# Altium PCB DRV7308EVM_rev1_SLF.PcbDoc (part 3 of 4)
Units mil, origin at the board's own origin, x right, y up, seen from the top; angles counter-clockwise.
Board outline 6187 x 6000 mil, 4 copper layers (Top Layer, Ground, Power, Bottom Layer), stack 61.2 mil thick; 306 components, 128 nets, 676 pads, 1026 vias.
Unrouted connection lines stored in the file: 208.
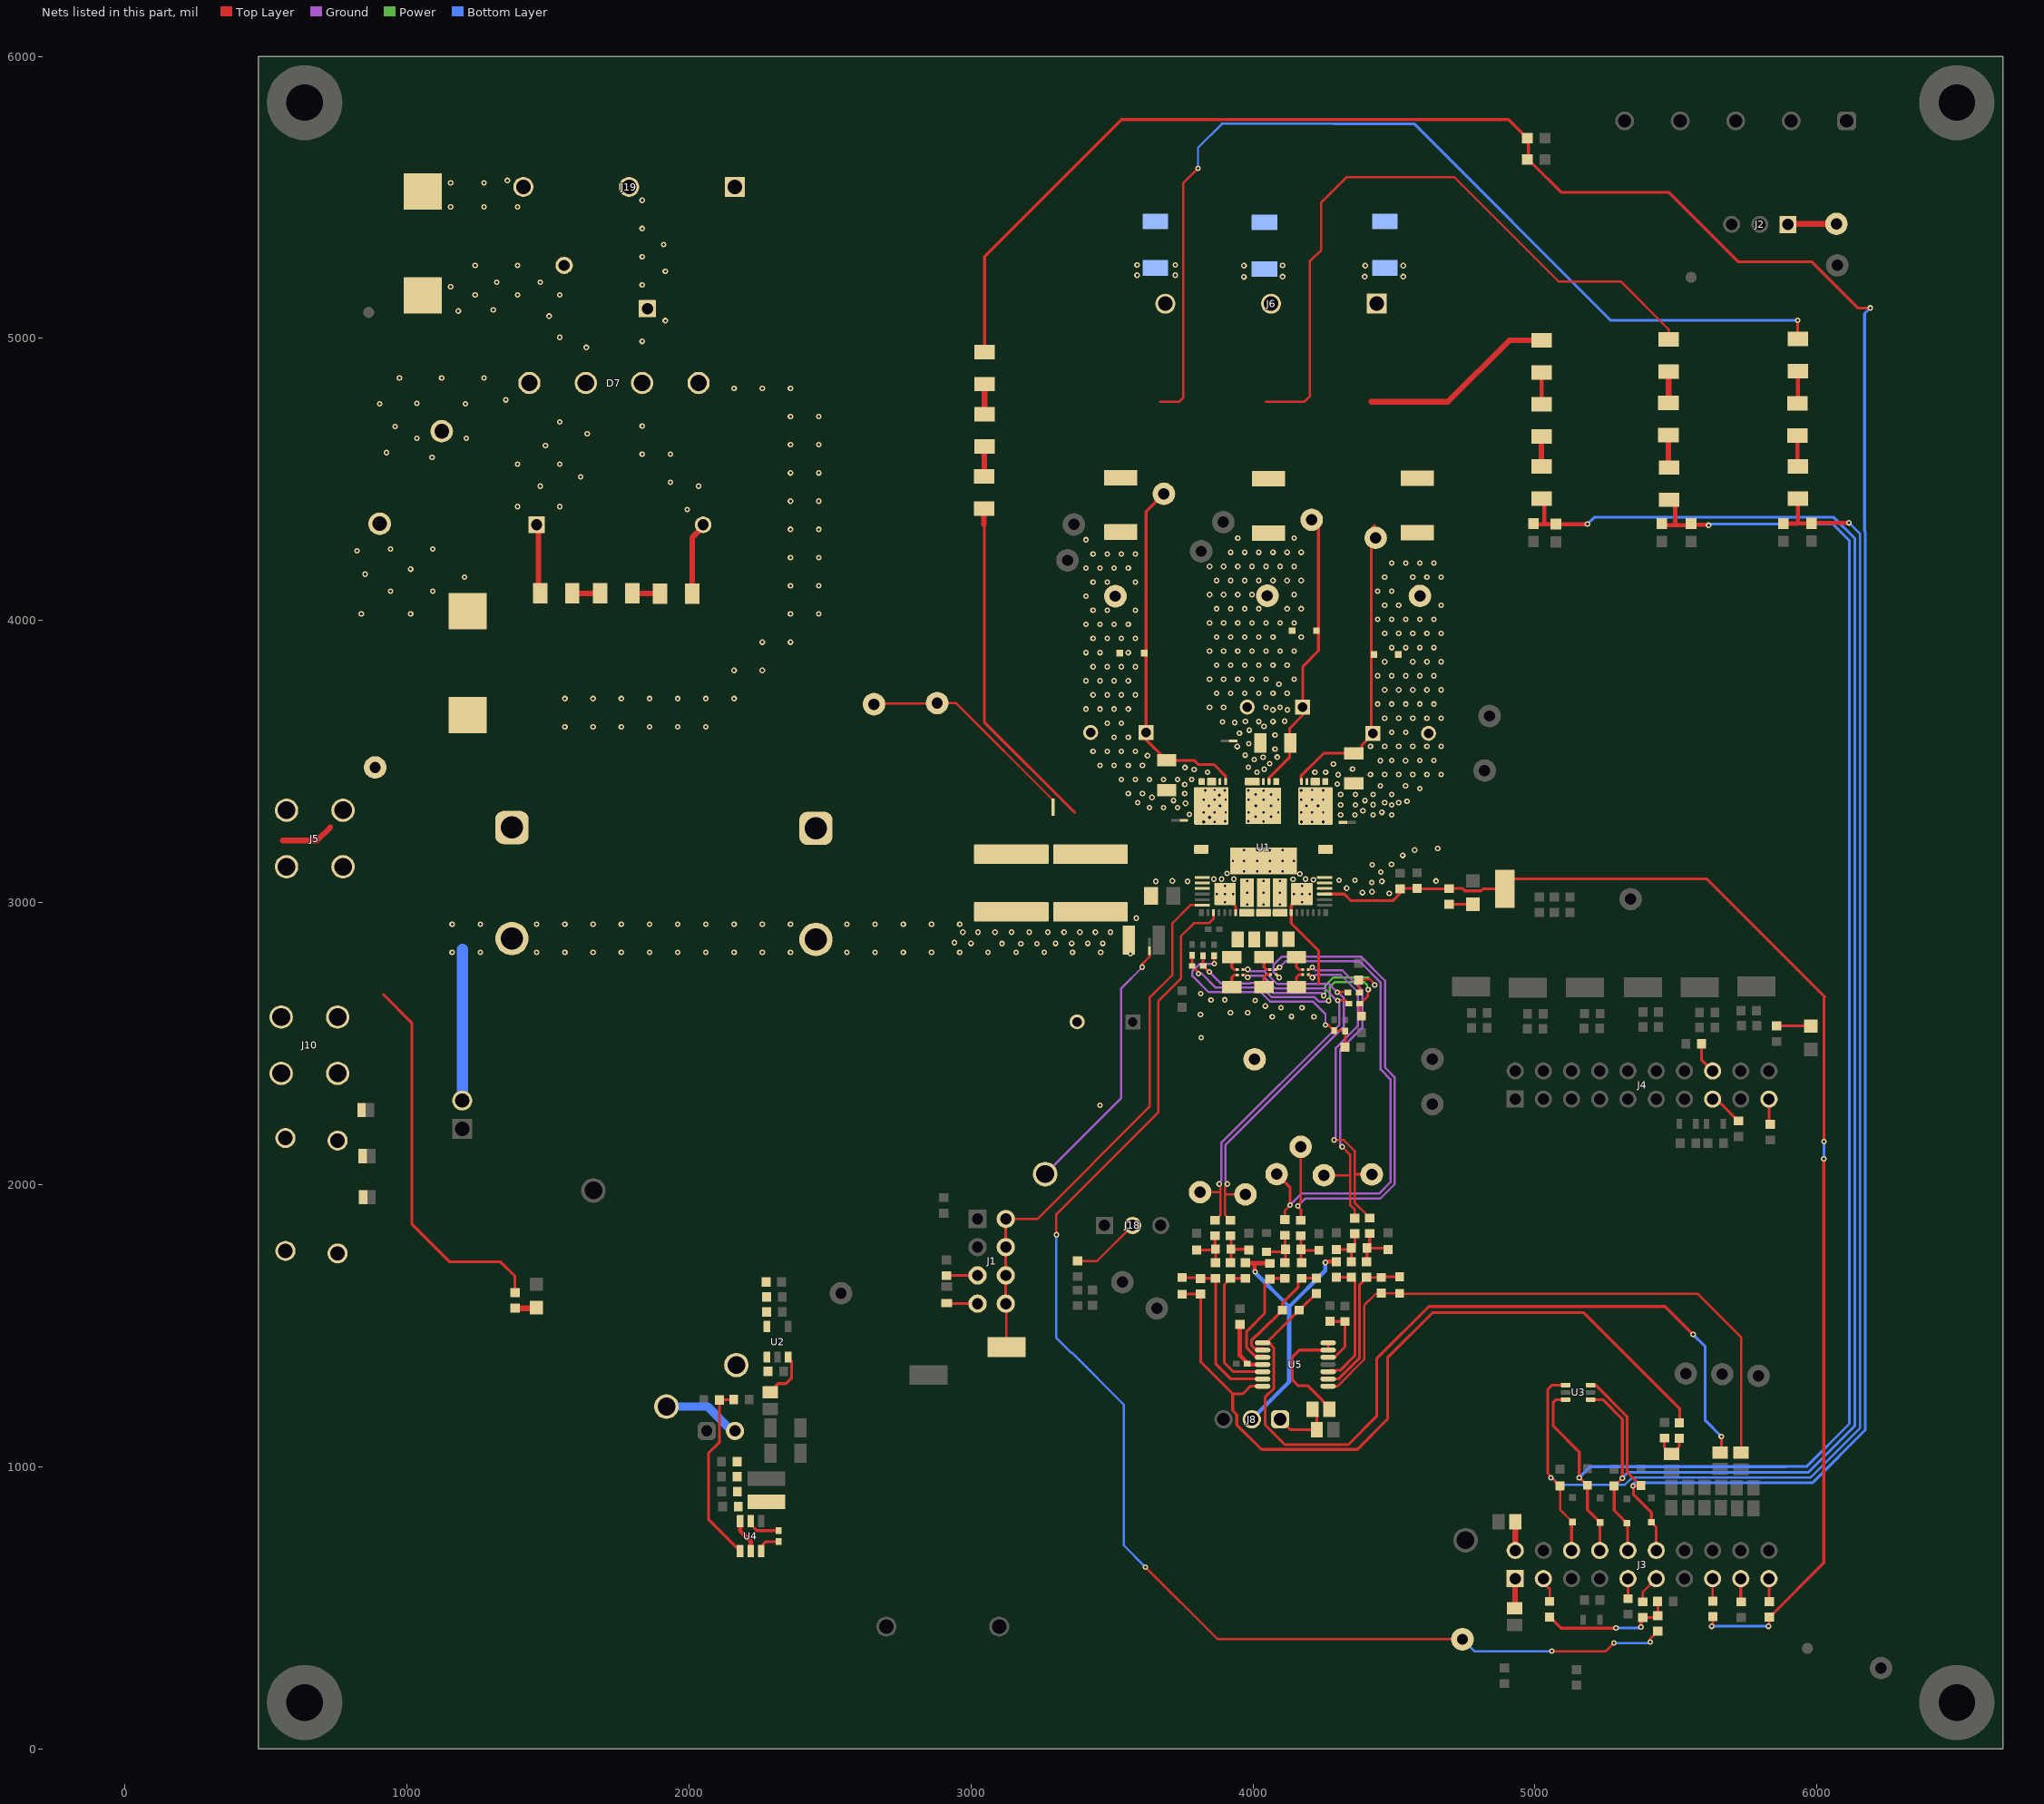
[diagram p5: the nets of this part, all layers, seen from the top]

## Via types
v1: diameter 20, hole 10, Top Layer to Bottom Layer, tented both sides, 563 vias
v2: diameter 20/20/20/20 (per signal layer), hole 10, Top Layer to Bottom Layer, tented both sides, 370 vias
v3: diameter 19.68, hole 7.87, Top Layer to Bottom Layer, tented both sides, 57 vias
v4: diameter 39.37, hole 19.68, Top Layer to Bottom Layer, tented both sides, 24 vias
v5: diameter 20/20/20/20 (per signal layer), hole 10, Top Layer to Bottom Layer, tented bottom, 12 vias

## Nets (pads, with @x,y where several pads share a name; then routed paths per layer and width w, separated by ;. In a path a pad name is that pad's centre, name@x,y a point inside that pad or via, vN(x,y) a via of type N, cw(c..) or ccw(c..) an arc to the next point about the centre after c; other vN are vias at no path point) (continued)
NetC1_2: C1.2 C59.1 D14.1 TP29.1 U1.48 | length 1252.7
  Top Layer w10: TP29.1@3684,4449 3621,4386 3621,3881 3621,3869.06 C59.1@3621,3603 3621,3577.15 C1.2@3694,3504.15 3790.85,3504.15 3805.61,3489.39 3861.82,3489.39 3902.58,3448.63 U1.48@3902.58,3428.66
NetC2_1: C2.1 L1.1 U4.2 | length 120.4
  Top Layer w10: U4.2@2218.7,806.82 2218.7,794.74 2240.27,773.17 2317.73,773.17 C2.1@2318,773.44
NetC2_2: C2.2 U4.6 | length 85.8
  Top Layer w10: U4.6@2256.11,700.52 2256.11,717.55 2272.63,734.07 C2.2@2318,734.07
NetC3_2: C3.2 C60.1 D16.1 TP32.1 U1.43 | length 984.9
  Top Layer w10: U1.43@4056.76,3428.66 4056.76,3441.76 4130.5,3515.5 4130.5,3566 4130.5,3618.15 4176.76,3664.41 4176.76,3693 4176.76,3837.76 4177,3838 4232,3893 4232,3964 TP32.1@4232,4341
NetC4_1: C4.1 J8.1 R14.2 | length 225.3
  Top Layer w10: J8.1@4095.7,1168 4132.7,1131 C4.1@4226.47,1131 4226.47,1189 R14.2@4211.47,1204
NetC5_2: C5.2 C61.1 D15.1 TP34.1 U1.41 | length 1089.8
  Top Layer w10: U1.41@4170.93,3428.66 4170.93,3449.52 4250.56,3529.15 4369,3529.15 4385.66,3545.8 4385.66,3557.81 4404,3576.15 4404,3578.43 C61.1@4425.57,3600 4419.15,3606.43 4419.15,3867 4419.15,4177 4419.15,4324.15 4431,4336
NetC7_1: C7.1 C29.1 C30.1 C31.1 J17.2 TP33.1 U4.3 U4.5 | length 400.6
  Top Layer w15: U4.3@2181.3,806.82 2181.3,773.86 2218.7,736.46 U4.5@2218.7,700.52
  Bottom Layer w30: TP33.1@1920,1213 2065.83,1213 2152.39,1126.44 J17.2@2163,1126.44
NetC11_1: C11.1 C12.2 R9.2 R10.1 | length 864.4
  Top Layer w8: C12.2@4374,2724.44 4376.37,2722.07 R9.2@4376.37,2681 ; C12.2@4374,2727.44 4415.24,2727.44 4420.9,2721.78 4420.9,2721 4431.61,2710.29 v1(4431.61,2707.04)
  Top Layer w10: R10.1@3823,2811.32 3823,2775.69 C11.1@3823.68,2775 3844.82,2753.87 v1(3845,2753.87)
  Ground w8: v1@3847.13,2753.87 v1(3845,2753.87) 3885.33,2713.54 3989.89,2713.54 3991.35,2715 4037.92,2715 4072.84,2680.08 4242.77,2680.08 4251.77,2671.08 v1(4250.5,2669.81)
  Power w8: v1(4250.5,2669.81) 4250.5,2673.05 4256.5,2679.05 4256.5,2705.89 4284.61,2734 4408.48,2734 4429.31,2713.17 4429.31,2712.59 4431.61,2710.29 v1(4431.61,2707.04)
NetC11_2: C11.2 C36.1 R11.2 R12.1 | length 888.5
  Top Layer w8: R11.2@4378.69,2642 4378.69,2603.84 C36.1@4385,2597.53 ; R11.2@4380.65,2642 4408.07,2669.42 4408.07,2690.72 v1(4408.78,2691.42)
  Top Layer w10: R12.1@3784,2812.32 3784.31,2812 C11.2@3784.31,2775 3807,2752.31 v1(3807,2748)
  Ground w8: v1(3807,2748) 3816,2748 3817,2749 3867.92,2698.08 4032.98,2698.08 4066.44,2664.62 4218.24,2664.62 4234.52,2648.35 v1@4259.39,2648.35
  Power w8: v1(4268,2652) 4268,2655.25 4271.96,2659.2 4271.96,2699.48 4291.01,2718.54 4393.59,2718.54 4404.99,2707.14 4404.99,2698.45 4408.78,2694.67 v1(4408.78,2691.42)
NetC17_1: C17.1 R46.1 R53.2 U5.2 | length 423.4
  Top Layer w10: U5.2@4034.12,1413.33 4038.85,1418.06 4006.77,1418.06 3994.56,1430.28 3994.56,1447.56 4013,1466 4015.47,1466 C17.1@4104.47,1555 4104.47,1580.36 4160.83,1636.71 4160.83,1656.69 4171.57,1667.44 R53.2@4172.56,1667.44 4173.68,1668.56 R46.1@4226.56,1668.56
NetC24_1: C24.1 R58.1 R60.2 U5.6 | length 612
  Top Layer w10: C24.1@3749,1670.53 3810.43,1670.53 R58.1@3814.26,1666.7 3815.14,1667.59 R60.2@3867.26,1667.59 3867.26,1364.99 3921.29,1310.96 U5.6@4034.12,1310.96
NetC28_1: C28.1 C33.1 R54.1 U2.5
NetC37_2: C37.2 C39.1 R52.2 R53.1 | length 162.2
  Top Layer w10: R52.2@4169.56,1818.44 4169.56,1770.56 C39.1@4170.12,1770 ; R53.1@4172.56,1722.56 4170.12,1725 C39.1@4170.12,1770 ; C37.2@4234,1767 4173.12,1767 C39.1@4170.12,1770
NetC38_2: C38.2 R47.1 U5.4 | length 205.9
  Top Layer w15: R47.1@3953.26,1504.59 3953.26,1394.62 3979.94,1367.93 C38.2@3979.94,1365.14 3982.94,1362.14 U5.4@4034.12,1362.14
NetC39_2: C39.2 C40.1 R55.2 R56.1 | length 169.3
  Top Layer w10: C40.1@4048.26,1761.68 4106.68,1761.68 C39.2@4115,1770 ; R56.1@4113.56,1722.56 4115,1724 C39.2@4115,1770 ; R55.2@4113.56,1820.44 4113.56,1771.44 C39.2@4115,1770
NetC41_2: C41.2 C42.1 R59.2 R60.1 | length 164.5
  Top Layer w10: C41.2@3800,1768.47 3864.03,1768.47 C42.1@3866.7,1771.14 ; R59.2@3865.26,1818.59 3865.26,1772.59 C42.1@3866.7,1771.14 ; R60.1@3867.26,1722.7 3867.26,1770.59 C42.1@3866.7,1771.14
NetC42_2: C42.2 C43.1 R61.2 R62.1 | length 162.7
  Top Layer w10: R62.1@3920.26,1722.7 3921.82,1724.26 C42.2@3921.82,1771.14 ; R61.2@3920.26,1818.59 3921.82,1817.03 C42.2@3921.82,1771.14 ; C43.1@3985,1768.47 3985,1770.59 3922.37,1770.59 C42.2@3921.82,1771.14
NetC44_2: C44.2 C45.1 R65.2 R66.1 | length 181.6
  Top Layer w10: R66.1@4402.56,1726.56 4404.12,1728.12 C45.1@4404.12,1775 ; R65.2@4414,1826.44 4414,1784.88 C45.1@4404.12,1775 ; C44.2@4479,1770 4474,1775 C45.1@4404.12,1775
NetC45_2: C45.2 C46.1 R67.2 R68.1 | length 159.7
  Top Layer w10: C46.1@4296,1770 4344,1770 C45.2@4349,1775 ; R68.1@4348.56,1726.56 4349,1727 C45.2@4349,1775 ; R67.2@4361,1826 4361,1787.98 4349,1775.98 C45.2@4349,1775
NetC50_1: C50.1 R64.1 R66.2 U5.9 | length 557.3
  Top Layer w8: R66.2@4403.44,1670.56 R64.1@4455.56,1670.56
  Top Layer w10: U5.9@4266.4,1310.96 4303.15,1310.96 4378.26,1386.07 4378.26,1645.37 4390.83,1657.94 4390.83,1660.69 4400.69,1670.56 R66.2@4403.44,1670.56 ; R64.1@4455.56,1670.56 4457.91,1672.91 C50.1@4520.3,1672.91
NetC52_2: C52.2 R8.1 R45.2 R129.2 | length 836.7
  Top Layer w8: R45.2@3862,2811.31 3862,2784 v1(3863,2783) ; v1(4257,2566) 4267.32,2566 R8.1@4288,2545.32 4326,2545.32 R129.2@4327,2544.31 4327,2487.56 C52.2@4326.44,2487
  Ground w8: v1(3863,2783) 3811.65,2783 3785.54,2756.89 3785.54,2739.11 3842.03,2682.62 4026.58,2682.62 4060.04,2649.16 4211.84,2649.16 4257,2604 v1(4257,2566)
NetC56_1: C56.1 D7.2 F1.1 R121.2 RV1.2 | length 248.4
  Top Layer w20: C56.1@1459.72,4339.36 1465.82,4333.26 1465.82,4102.09 R121.2@1471.91,4096
  other v1: 1473,4476 1616,4509 1491,4620 1639,4662 1636,4968 1504,5079 1182,5097 1306,5101 1155,5183 1318,5199 1473,5199 1241.77,5258.77 1391.77,5258.77
  other v2: 1391.77,4403.7 1541.77,4403.7 1391.77,4553.7 1541.77,4553.7 1541.77,4703.7 1541.77,5003.7 1241.77,5153.7 1391.77,5153.7 1541.77,5153.7
NetC56_2: C56.2 D7.3 J19.2 R122.1 RV1.1 | length 260.4
  Top Layer w20: R122.1@2011.5,4095 2011.5,4293.95 2050.28,4332.72 C56.2@2050.28,4339.36
  other v1: 1994,4393 2034,4476 1916,5063 1916,5238 1910,5333
  other v2: 1934,4489.55 1834,4589.55 1934,4589.55 1834,4689.55 1834,4989.55 1834,5189.55 1834,5289.55 1834,5389.55 1834,5489.55
NetD2_2: D2.2 R15.2 | length 85.1
  Top Layer w10: R15.2@4695,2993.86 4779.78,2993.86 D2.2@4780,2994.08
NetD3_2: D3.2 R16.2 | length 65.5
  Top Layer w20: R16.2@1394.56,1561.34 1456.34,1561.34 D3.2@1459,1564
NetD4_2: D4.2 R17.2 | length 132.1
  Top Layer w10: R17.2@5848.99,2555.69 R17.2@5856.54,2563.24 ; R17.2@5857.19,2562.59 5977.45,2562.59 D4.2@5978.28,2561.76
NetD7_1: D7.1 RT1.1
  other v1: 1089,4578 927,4595 1035,4646 1210,4646 958,4688 903,4768 1207,4768 1035,4770 1350,4782
  other v2: 973,4859.82 1123,4859.82 1273,4859.82
NetF1_2: F1.2 J19.3
  other v1: 1155,5466 1273,5466 1391.77,5466 1155,5551 1273,5551 1356,5560
NetF2_1: F2.1 RT1.2
  other v1: 838,4023 1013,4023 1204,4154 852,4164 1013,4182 823,4247
  other v2: 941.77,4103.7 1091.77,4103.7 941.77,4253.7 1091.77,4253.7
NetJ1_5: J1.5 R43.2 | length 110.2
  Top Layer w10: R43.2@2913.23,1677.44 2913.79,1678 J1.5@3023.23,1678
NetJ1_7: J1.7 R44.2 | length 109.6
  Top Layer w10: R44.2@2914.23,1579.47 2915.7,1578 J1.7@3023.23,1578
NetJ2_1: J2.1 TP52.1 | length 181.1
  Top Layer w20: J2.1@5897,5404 5899,5406 TP52.1@6069,5406 TP52.1@6074.87,5411.87
NetJ3_1: J3.1 R13.2 | length 105.7
  Top Layer w20: R13.2@4927.82,498.13 4929.82,500.13 J3.1@4929.82,603
NetJ3_2: J3.2 R36.1 | length 102.2
  Top Layer w20: J3.2@4929.82,703 4929.93,703.11 4929.93,804.59 R36.1@4930.35,805
NetJ3_3: J3.3 R135.2 | length 89.8
  Top Layer w8: J3.3@5029.82,603 5029.82,588.65 5051.7,566.77 R135.2@5051.7,522.25
NetJ3_9: J3.9 R2.2 | length 70.9
  Top Layer w10: J3.9@5329.82,603 5329.82,532.23 R2.2@5329.93,532.12
NetJ3_11: J3.11 R137.2 | length 101.8
  Top Layer w8: R137.2@5382.7,520.69 5382.7,555.88 J3.11@5429.82,603
NetJ3_15: J3.15 R48.2 | length 80.3
  Top Layer w8: J3.15@5629.82,603 5629.82,524.12 R48.2@5630.82,523.12
NetJ3_17: J3.17 R49.2 | length 82.9
  Top Layer w10: J3.17@5729.82,603 5729.82,521.56 R49.2@5730.82,520.56
NetJ3_19: J3.19 R50.2 | length 81.9
  Top Layer w10: J3.19@5829.82,603 5829.82,522.56 R50.2@5830.82,521.56
NetJ4_15: J4.15 R138.2 | length 124
  Top Layer w10: J4.15@5629.82,2303 5642.93,2303 5660.84,2285.09 5661.15,2285.09 5720.56,2225.69 5721.7,2225.69 R138.2@5721.64,2225.58
NetJ4_16: J4.16 R139.1 | length 112.1
  Top Layer w10: R139.1@5590.26,2498.69 5590.26,2442.56 J4.16@5629.82,2403
NetJ4_19: J4.19 R51.2 | length 91.5
  Top Layer w10: J4.19@5829.82,2303 5829.82,2218.56 R51.2@5834.82,2213.56
NetJ8_2: J8.2 R57.2 R63.2 R69.2 | length 998
  Top Layer w15: R63.2@3973.26,1722.7 3974.33,1721.63 4005.26,1721.63 ; v1(4007.26,1691.14) 4005.26,1693.14 4005.26,1721.63 ; R57.2@4060.56,1720.56 4059.49,1721.63 4005.26,1721.63 ; v1(4256.56,1724) 4259.12,1726.56 R69.2@4295.56,1726.56
  Bottom Layer w15: J8.2@3995.7,1168 4128.26,1300.56 4128.26,1566.91 ; v1(4007.26,1691.14) 4007.26,1687.91 4128.26,1566.91 ; v1(4256.56,1724) 4256.56,1695.21 4128.26,1566.91
NetJ18_2: J18.2 R118.2 | length 247.2
  Top Layer w8: R118.2@3378,1729 3447,1729 J18.2@3573,1855
NetNT12_1: NT12.1 TP40.1 TP41.1 | length 789.1
  Top Layer w8: TP41.1@2656,3703 2658,3705 2878,3705 TP40.1@2880,3707 2947,3707 3291,3363 NT12.1@3291,3353
NetNT13_1: NT13.1 TP50.1 | length 945.7
  Top Layer w8: v1(3607,2771) 3607,2782 3633,2808 NT13.1@3633,2829
  Ground w8: TP50.1@3263,2037 3532.84,2306.84 3532.84,2695.84 v1@3608,2771
NetR1_1: R1.1 R4.2 U4.4 | length 650.5
  Top Layer w10: R1.1@2158.44,1237.44 2108.56,1237.44 R4.2@2107.56,1236.44 2108.56,1235.44 2108.56,1087 2069,1047.44 2069,812.82 U4.4@2181.3,700.52
NetR14_1: R14.1 U5.13 U5.14 | length 421.7
  Top Layer w10: U5.14@4266.4,1438.92 U5.13@4266.4,1413.33 4164.78,1413.33 4139.06,1387.61 4139.06,1308.39 4160.73,1286.73 4194.92,1286.73 4245.17,1236.49 4245.17,1235.27 4270.53,1209.91 R14.1@4270.53,1204
NetR22_1: R22.1 R122.2 | length 98.7
  Top Layer w20: R22.1@1799.09,4096 1896.33,4096 R122.2@1897.33,4095
NetR22_2: R22.2 R121.1 | length 98.8
  Top Layer w20: R121.1@1586.09,4096 R22.2@1684.91,4096
NetR56_2: R56.2 R57.1 U5.3 | length 412.6
  Top Layer w10: U5.3@4034.12,1387.73 4038.85,1392.47 4006.77,1392.47 3977.56,1421.69 3977.56,1479.43 4041.26,1543.13 4041.26,1646.14 4048.83,1653.71 4048.83,1654.69 4059.57,1665.44 R57.1@4060.56,1665.44 4062.56,1667.44 R56.2@4113.56,1667.44
NetR62_2: R62.2 R63.1 U5.5 | length 563.1
  Top Layer w10: U5.5@4034.12,1336.55 3930.54,1336.55 3898.26,1368.84 3898.26,1645.59 R62.2@3920.26,1667.59 ; R62.2@3920.26,1667.59 R63.1@3973.26,1667.59 R62.2@3920.26,1667.59
NetR68_2: R68.2 R69.1 U5.10 | length 454.9
  Top Layer w10: U5.10@4266.4,1336.55 4271.13,1341.29 4309.43,1341.29 4361.26,1393.11 4361.26,1658.74 R68.2@4348.56,1671.44 R69.1@4295.56,1671.44
NetR70_2: R70.2 R78.1 R79.1 | length 134.8
  Top Layer w10: R78.1@5458.82,1101.44 5458.82,1069.53 R70.2@5483.82,1044.53 5511.82,1072.53 R79.1@5511.82,1100.44
NetR73_1: R73.1 R74.2 U5.12 | length 218.3
  Top Layer w10: U5.12@4266.4,1387.73 4289.01,1387.73 4326.26,1424.98 R74.2@4326.26,1514.59 4274.26,1514.59 R73.1@4273.26,1515.59
NetR91_1: R91.1 R98.2 | length 106.8
  Top Layer w20: R91.1@3047,4510.09 3047,4615.46 R98.2@3048,4616.46
NetR92_1: R92.1 R110.2 | length 115.9
  Top Layer w15: R110.2@5023.3,4766.91 R92.1@5023.3,4878.91
  Top Layer w20: R92.1@5023.3,4878.91 R92.1@5023.3,4882.85
NetR93_1: R93.1 R111.2 | length 115.6
  Top Layer w20: R111.2@5473,4767.03 5472.62,4767.41 5474,4768.79 R93.1@5474,4881.91
NetR94_1: R94.1 R112.2 | length 114.2
  Top Layer w15: R112.2@5931,4770.09 5932,4771.09 R94.1@5932,4883.91
NetR98_1: R98.1 R113.2 | length 112.6
  Top Layer w20: R113.2@3047,4841.85 R113.2@3048,4840.85 ; R98.1@3048,4726.69 R98.1@3048,4730.63 R113.2@3048,4837.91
NetR110_1: R110.1 R116.2 | length 110.2
  Top Layer w20: R116.2@5023,4546.61 5023,4656.38 R110.1@5023.3,4656.68
NetR111_1: R111.1 R130.2 | length 115.5
  Top Layer w20: R111.1@5473,4656.8 5473,4544.09 R130.2@5475,4542.09
NetR112_1: R112.1 R134.2 | length 114.2
  Top Layer w15: R134.2@5931,4543.15 R112.1@5931,4655.91
  Top Layer w20: R134.2@5931,4543.15 R134.2@5932,4542.15
nFAULT: R15.1 R41.1 R48.1 R50.1 R127.2 TP45.1 U1.26 | length 4560.6
  Top Layer w10: U1.26@4254.12,3030.04 4323.54,3030.04 4347.1,3006.48 4495.8,3006.48 4496,3006.28 4522,3032.28 R127.2@4522,3048.82 ; R127.2@4522,3050.44 R41.1@4582,3050.44 4583.46,3048.98 R15.1@4695,3048.98 ; R15.1@4695,3050.44 4742.1,3050.44 4751.41,3041.14 4808.59,3041.14 4815.45,3048 TP45.1@4893,3048 4893,3053.34 4923,3083.34 5609.73,3083.34 6028,2665.06 6025,2662.06 v1(6025,2152.69) ; v1(5626.82,434) 5630.82,438 R48.1@5630.82,468 ; v1(5827.82,434) 5830.82,437 R50.1@5830.82,466.44 5831.8,466.44 6024,658.64 v1(6024,2091.69)
  Bottom Layer w10: v1(5626.82,434) v1(5827.82,434) ; v1(6024,2091.69) 6025,2092.69 v1(6025,2152.69)
OUT_A: C62.1 J6.3 L2.2 R94.2 | length 3506.6
  Top Layer w8: 3670.2,4775 3737,4775 3753,4791 3753,5551 v1(3805,5603)
  Top Layer w10: R94.2@5932,5004.3 v1(5932,5064)
  Bottom Layer w8: v1(3805,5603) 3805,5676 3890,5761 4288,5761
  Bottom Layer w10: 4288,5761 4571,5761 5268,5064 v1(5932,5064)
  other v5: 3589,5224 3725,5224 3589,5260 3725,5260
OUT_B: C63.1 J6.2 L3.2 R93.2 | length 2397.7
  Top Layer w8: 4045,4775 4182,4775 4201.09,4794.09 4201.09,5273.09 4242,5314 4242,5482 4332,5572 4713,5572 5083,5202 5304,5202 5474,5032 R93.2@5474,4996.09
  other v5: 3968,5218 4105,5219 3968,5258 4105,5259
OUT_C: C64.1 J6.1 L4.2 R92.2 | length 693.8
  Top Layer w20: 4419.8,4775 4691,4775 4909.09,4993.09 R92.2@5023.3,4993.09
  other v5: 4396,5219 4533,5219 4398,5258 4533,5258
OUTA: C1.1 C59.2 D14.2 L2.1 NT9.1 TP1.1 U1.49 U1.50 U1.51 U1.52 U1.53 U1.54 U1.55 U1.56 U1.57 U1.@3851.96,3342.48 U1.@3853.37,3428.66
  other v1: 3632.84,3336 3682.84,3336 3732.84,3336 3557.84,3386 3607.84,3386 3757.84,3386 3532.84,3436 3582.84,3436 3632.84,3436 3682.84,3436 3732.84,3436 3782.84,3436 3457.84,3486 3507.84,3486 3557.84,3486 3607.84,3486 3432.84,3536 3482.84,3536 3532.84,3536 3582.84,3536 3507.84,3586 3557.84,3586 3482.84,3636 3532.84,3636 3407.84,3686 3457.84,3686 3507.84,3686 3557.84,3686 3432.84,3736 3482.84,3736 3532.84,3736 3582.84,3736 3407.84,3786 3457.84,3786 3507.84,3786 3557.84,3786 3432.84,3836 3482.84,3836 3532.84,3836 3582.84,3836 3407.84,3886 3457.84,3886 3557.84,3886 3432.84,3936 3482.84,3936 3532.84,3936 3582.84,3936 3407.84,3986 3457.84,3986 3507.84,3986 3557.84,3986 3432.84,4036 3482.84,4036 3582.84,4036 3407.84,4086 3432.84,4136 3482.84,4136 3582.84,4136 3407.84,4186 3457.84,4186 3507.84,4186 3557.84,4186 3432.84,4236 3482.84,4236 3532.84,4236 3582.84,4236 3407.84,4286
  other v2: 3825.14,3285.83 3901.5,3287.8 3846,3302 3774,3312.29 3843.33,3342.48 3883,3343 3760.72,3351.56 3591.15,3353.7 3718,3361.58 3641.84,3372.5 3880.5,3380.58 3831.28,3397.17 3900,3397.17 3757.84,3418.82 3838.7,3462 3791.29,3471.5 3758.89,3478.54 3625.88,3520.75
  other v3: 3864.12,3285.83 3825.14,3319.84 3864.12,3319.84 3903.09,3319.84 3825.14,3365.12 3864.12,3365.12 3903.09,3365.12 3864.12,3399.13
OUTB: C3.1 C60.2 D16.2 L3.1 NT10.1 TP2.1 U1.42 U1.44 U1.45 U1.46 U1.47 U1.72 U1.@3997.7,3428.66
  other v1: 4014,3462 4039.76,3472.32 3984,3480 4059.3,3492.63 4004.53,3506.56 4036,3515.15 4086,3515.5 3972,3522.45 4078,3544 3944,3553 3985,3563 4078,3594 3952,3600 3986.85,3611.01 4039,3624.01 3935.07,3638.1 3892.2,3640.46 3973.21,3642 4021,3641.51 4071,3641.51 4112,3643 4070.98,3683 4122.12,3683 3846,3691.51 3896,3691.51 4046,3691.51 4096,3691.51 3871,3741.51 3921,3741.51 3971,3741.51 4021,3741.51 4071,3741.51 4121,3741.51 4092,3773.7 3846,3791.51 3896,3791.51 3946,3791.51 3996,3791.51 4046,3791.51 4146,3791.51 3871,3841.51 3921,3841.51 3971,3841.51 4021,3841.51 4071,3841.51 4121,3841.51 3846,3891.51 3896,3891.51 3946,3891.51 3996,3891.51 4046,3891.51 4096,3891.51 4146,3891.51 3871,3941.51 3921,3941.51 3971,3941.51 4021,3941.51 4071,3941.51 4171,3941.51 3846,3991.51 3896,3991.51 3946,3991.51 3996,3991.51 4046,3991.51 4096,3991.51 4146,3991.51 3871,4041.51 3921,4041.51 3971,4041.51 4021,4041.51 4121,4041.51 4171,4041.51 3846,4091.51 3896,4091.51 3946,4091.51 3996,4091.51 4146,4091.51 3871,4141.51 3921,4141.51 3971,4141.51 4021,4141.51 4071,4141.51 4121,4141.51 4171,4141.51 3846,4191.51 3896,4191.51 3946,4191.51 3996,4191.51 4046,4191.51 4096,4191.51 4146,4191.51 3921,4241.51 3971,4241.51 4021,4241.51 4071,4241.51 4121,4241.51 4171,4241.51 3946,4291.51 4146,4291.51
  other v2: 3984,3287.8 4009.9,3304.29 4064.38,3304.29 4010.01,3342.48 4064,3342.48 4009.9,3383 4064.38,3383 3984,3397.17
  other v3: 4037.07,3287.8 3984.39,3319.84 4037.07,3319.84 4089.75,3319.84 3984.39,3365.12 4037.07,3365.12 4089.75,3365.12 4037.07,3397.17
OUTC: C5.1 C61.2 D15.2 L4.1 NT11.1 TP3.1 U1.32 U1.33 U1.34 U1.35 U1.36 U1.37 U1.38 U1.39 U1.40 U1.@4220.77,3428.66 U1.@4222.18,3342.48
  other v1: 4311,3311 4361.77,3311 4426,3311 4492,3311 4457,3319.84 4389.76,3325.32 4311,3346 4363,3346 4492,3346 4426,3347 4466.77,3353.7 4516.77,3353.7 4546,3359 4396.52,3361.58 4311,3383 4363,3383 4426,3383 4492,3383 4591.77,3403.7 4452,3414 4541,3414 4299,3420 4302,3453 4416.77,3453.7 4466.77,3453.7 4516.77,3453.7 4566.77,3453.7 4616.77,3453.7 4666.77,3453.7 4219.39,3462.08 4257.56,3462.08 4353,3473 4285.07,3491.1 4452,3503 4541,3503 4491.77,3503.7 4591.77,3503.7 4641.77,3503.7 4416.77,3553.7 4466.77,3553.7 4516.77,3553.7 4566.77,3553.7 4616.77,3553.7 4666.77,3553.7 4491.77,3603.7 4541.77,3603.7 4466.77,3653.7 4516.77,3653.7 4566.77,3653.7 4616.77,3653.7 4666.77,3653.7 4441.77,3703.7 4491.77,3703.7 4541.77,3703.7 4591.77,3703.7 4641.77,3703.7 4466.77,3753.7 4516.77,3753.7 4566.77,3753.7 4616.77,3753.7 4666.77,3753.7 4441.77,3803.7 4491.77,3803.7 4541.77,3803.7 4591.77,3803.7 4641.77,3803.7 4466.77,3853.7 4566.77,3853.7 4616.77,3853.7 4666.77,3853.7 4491.77,3903.7 4541.77,3903.7 4591.77,3903.7 4641.77,3903.7 4466.77,3953.7 4516.77,3953.7 4566.77,3953.7 4616.77,3953.7 4666.77,3953.7 4441.77,4003.7 4491.77,4003.7 4541.77,4003.7 4591.77,4003.7 4641.77,4003.7 4466.77,4053.7 4516.77,4053.7 4666.77,4053.7 4441.77,4103.7 4491.77,4103.7 4466.77,4153.7 4566.77,4153.7 4616.77,4153.7 4666.77,4153.7 4491.77,4203.7 4541.77,4203.7 4591.77,4203.7 4641.77,4203.7
  other v2: 4171.56,3285.83 4249,3285.83 4188.88,3342.48 4230.61,3342.48 4249,3397.17 4171.05,3397.85
  other v3: 4210.02,3285.83 4171.05,3319.84 4210.02,3319.84 4249,3319.84 4171.05,3365.12 4210.02,3365.12 4249,3365.12 4210.02,3399.13
PE: J19.1
PGND: C6.1 C8.1 C9.1 C10.1 C57.2 C58.2 C62.2 C63.2 C64.2 C67.2 D7.4 J9.2 J10.1 NT1.2 NT2.2 NT4.1 NT6.1 NT8.1 NT14.2 R3.1 R6.1 R16.1 R37.1 TP12.1 TP12.2 TP13.1 TP13.2 TP17.1 U1.7 U1.17 U1.27 U1.28 U1.29 U1.60 U1.61 U1.62 U1.66 U1.70 U1.71 | length 2575.3
  Top Layer w10: 916.49,2673.51 1017,2573 1017,2381.22 1016.78,2381 1016.78,1860.22 1151.3,1725.7 1332.3,1725.7 1383,1675 R16.1@1383,1617 ; R3.1@3925,2699.85 3925,2735 3933,2743 NT6.1@3944,2743 ; U1.66@3933,2993 3938.65,2987.35 U1.7@3938.65,2964.09 ; U1.71@4000.69,3150.51 4113.92,3150.51 U1.71@4135.5,3128.94 ; R6.1@4038.82,2699.85 4038.82,2737.71 4046.11,2745 NT4.1@4063,2745 ; U1.70@4139,2996 4135.5,2992.5 U1.17@4135.5,2964.09 4135.5,2926.34 4233,2828.84 4233,2713.33 4233.33,2713 ; R37.1@4154,2699.85 4154,2735 4163,2744 NT8.1@4176,2744
  Bottom Layer w40: J9.2@1196,2298 1196,2834
  other v1: 3458,2281 3816,2521 4068.34,2595 4216,2595 4136,2596 3814,2603 3920.19,2609 3981,2609 4099,2627 4174,2627 4044,2633 4008,2653 3851.06,2654 3899.63,2655 3815,2677 3565,2819 1160,2823 1260,2823 1460,2823 1560,2823 1660,2823 1760,2823 1860,2823 1960,2823 2060,2823 2160,2823 2260,2823 2360,2823 2560,2823 2660,2823 2760,2823 2860,2823 2960,2823 3060,2823 3160,2823 3260,2823 3360,2823 3460,2823 3177,2853.69 3234,2854 3000,2855 3110,2854.42 3300,2855 3357,2855 3414,2855 3467,2855 2941,2858 2971,2895 3025,2895 3085,2895 3144,2895 3207,2895 3273,2895 3330,2895 3386,2895 3441,2895 3495,2895 1160,2923 1260,2923 1460,2923 1560,2923 1660,2923 1760,2923 1860,2923 1960,2923 2060,2923 2160,2923 2260,2923 2360,2923 2560,2923 2660,2923 2760,2923 2860,2923 2960,2923 3586,2944.87 4483,3032.28 4388,3035 4422,3038 4332.08,3051 4421,3071.19 3655,3075 3768.35,3075 4457,3075 3714,3076.76 4649,3076.38 4304.85,3079 4362,3078.71 4214.24,3081 4141.99,3082 3861,3083 3888.57,3083 3932,3083.19 4186,3083 4166,3102 3908,3103 4453,3107.81 4423,3134 4491,3135 4531,3167 4573,3186 4655,3192 1560,3623 1660,3623 1760,3623 1860,3623 1960,3623 2060,3623 1560,3723 1660,3723 1760,3723 1860,3723 1960,3723 2060,3723 2160,3723 2160,3823 2260,3823 2260,3923 2360,3923 2360,4023 2460,4023 2360,4123 2460,4123 2360,4223 2460,4223 2360,4323 2460,4323 2360,4423 2460,4423 2360,4523 2460,4523 2360,4623 2460,4623 2360,4723 2460,4723 2160,4823 2260,4823 2360,4823
  other v3: 3900.65,3001.14 4173.49,3001.14 3872.31,3030.2 3900.65,3030.2 3929,3030.2 4145.14,3030.2 4173.49,3030.2 4201.83,3030.2 3900.65,3059.21 4173.49,3059.21 3968.57,3110.24 4014.24,3110.24 4059.91,3110.24 4105.57,3110.24 3928.8,3147.83 3968.57,3147.83 4014.24,3147.83 4059.91,3147.83 4105.57,3147.83 4145.34,3147.83 3968.57,3185.43 4014.24,3185.43 4059.91,3185.43 4105.57,3185.43
SLA: NT5.1 R3.2 R5.2 U1.8 U1.9 U1.10 U1.67 U1.@3978.02,2964.09 | length 76.4
  Top Layer w8: R3.2@3925,2806.15 R3.2@3942.93,2806.15
  Top Layer w10: R3.2@3925,2806.15 3925,2770 3933,2762 NT5.1@3944,2762
  other v3: 3979,2993.66 3979,3035 3979,3076.38
SLB: NT3.1 R5.1 R6.2 R21.2 U1.11 U1.12 U1.13 U1.68 U1.@4037.07,2964.09 | length 60.5
  Top Layer w10: R6.2@4038.82,2806.15 4039,2805.97 4039,2770 4047,2762 NT3.1@4060,2762
  other v3: 4037.07,2993.66 4037.07,3035 4037.07,3076.38
SLC: NT7.1 R21.1 R37.2 U1.14 U1.15 U1.16 U1.69 U1.@4096.13,2964.09 | length 60.9
  Top Layer w10: R37.2@4154,2806.15 4154,2771 4163,2762 NT7.1@4176,2762
  other v3: 4095.14,2993.66 4095.14,3035 4095.14,3076.38
SLEW: J1.2 J1.4 J1.6 J1.8 TP24.1 U1.65 | length 1946.6
  Top Layer w8: J1.8@3123.23,1578 3126,1575.23 TP24.1@3126,1424 ; J1.2@3123.23,1878 3235,1878 3633,2276 3633,2661.79 3714,2742.79 3714,2926.73 3777.94,2990.67 U1.65@3820.02,2990.67
  Top Layer w10: J1.8@3123.23,1578 J1.6@3123.23,1678 J1.4@3123.23,1778 J1.2@3123.23,1878
SNA: NT6.2 R11.1 R59.1 TP31.1 | length 1464.2
  Top Layer w8: TP31.1@3812.26,1973.14 3884.26,1973.14 3885.26,1972.14 ; R59.1@3865.26,1873.7 3885.26,1893.7 3885.26,1972.14 ; v1(3880,2002) 3880,1998.75 3885.26,1993.5 3885.26,1972.14 ; NT6.2@3964,2743 3973,2743 v1(3981,2735) ; v1(4300,2653) 4328.32,2653 R11.1@4339.32,2642
  Ground w8: v1(3880,2002) 3880,2005.15 3887.54,2012.69 3887.54,2147.54 4306,2566 4306,2643.75 4300,2649.75 v1(4300,2653) 4297.65,2653 4255.11,2695.54 4079.25,2695.54 4033.79,2741 3987,2741 v1(3981,2735)
SNB: NT4.2 R52.1 TP14.1 | length 1891.1
  Top Layer w8: NT4.2@4083,2745 4093,2735 v1(4093,2734) ; v1(4159.35,1924.36) 4159.35,1927.61 4169.19,1937.45 TP14.1@4169.19,2134
  Top Layer w10: v1(4159.35,1924.36) 4159.35,1921.66 4170.12,1910.89 4170.12,1874.12 R52.1@4169.56,1873.56
  Ground w8: v1(4093,2734) 4072.54,2754.46 4072.54,2778.89 4101.03,2807.38 4383.48,2807.38 4468.53,2722.33 4468.53,2414.33 4503,2379.86 4503,2002.07 4450.83,1949.9 4184.89,1949.9 v1(4159.35,1924.36)
SNC: NT8.2 R65.1 TP54.1 | length 1178.6
  Top Layer w8: v1(4287.54,2158.21) 4321.48,2158.21 4360.26,2119.44 4360.26,1935.3 4401.27,1894.29 4401.27,1893.31 4413.02,1881.56 R65.1@4414,1881.56
  Top Layer w10: NT8.2@4196,2744 4201,2744 v1(4211,2734) ; 4361.26,2037.14 4362.26,2036.14 TP54.1@4421.26,2036.14
  Ground w8: v1(4211,2734) 4212.15,2734 4221.69,2743.54 4311,2743.54 4372,2682.54 4372,2562.4 4293.54,2483.94 4293.54,2167.46 4287.54,2161.46 v1(4287.54,2158.21)
SOA: C24.2 R58.2 R79.2 U5.7 | length 2825.3
  Top Layer w10: C24.2@3749,1611.47 3814.14,1611.47 R58.2@3814.26,1611.59 3814.26,1372.1 3928.02,1258.34 ; U5.7@4034.12,1285.37 3991.3,1285.37 3964.27,1258.34 3928.02,1258.34 ; R79.2@5511.82,1155.56 5512.82,1156.56 5512.82,1206 5173.24,1545.57 4636.51,1545.57 4477,1386.06 4477,1168 4370,1061 4030.08,1061 3942.62,1148.46 3942.62,1183.98 3928.02,1198.58 3928.02,1258.34
SOB: C17.2 R46.2 R71.2 U5.1 | length 2951.9
  Top Layer w10: U5.1@4034.12,1438.92 4050.73,1438.92 4054.29,1442.48 4054.29,1445.76 C17.2@4163.53,1555 4174.28,1565.75 4176.32,1565.75 4224.02,1613.44 R46.2@4225,1613.44 ; U5.1@4054.9,1438.92 4054.36,1438.37 4054.36,1435.42 4060.22,1435.42 4073.67,1421.96 4073.67,1276.73 4042.77,1245.83 4042.77,1148.51 4113.28,1078 4338,1078 4438.26,1178.26 4438.26,1382.5 4623.55,1567.78 5461.47,1567.78 v1(5560.84,1468.41) ; R71.2@5656.82,1050.53 5660.82,1054.53 v1(5660.82,1107)
  Bottom Layer w10: v1(5560.84,1468.41) 5603.71,1425.54 5603.71,1164.1 v1(5660.82,1107)
SOC: C50.2 R64.2 R72.2 U5.8 | length 2183.2
  Top Layer w8: U5.8@4266.4,1285.37 4300.19,1285.37 4394.26,1379.44 4394.26,1571.59 4436.26,1613.59 4453.14,1613.59 R64.2@4455,1615.44 ; R64.2@4459.11,1614.47 C50.2@4520,1614.47 ; C50.2@4520,1613.59 5576.35,1613.59 5730.82,1459.12 R72.2@5730.82,1049.53
SPA: NT5.2 R9.1 R61.1 TP47.1 | length 1495.6
  Top Layer w8: v1(3909,2002) 3909,2000.06 3900.26,1991.31 3900.26,1966.14 ; R61.1@3920.26,1873.7 3900.26,1893.7 3900.26,1966.14 ; NT5.2@3964,2762 3976.56,2762 3977.56,2763 v1(3981,2763) ; TP47.1@3973.26,1965.14 3901.26,1965.14 3900.26,1966.14 ; v1(4299,2682) R9.1@4333.24,2682 ; R9.1@4333.24,2682 4337,2678.24 R9.1@4337,2681 4336,2682 R9.1@4333.24,2682
  Ground w8: v1(3909,2002) 3909,2005.25 3903,2011.25 3903,2141.14 4321.46,2559.6 4321.46,2661.89 4301.35,2682 v1(4299,2682) 4270,2711 4085.65,2711 4040.19,2756.46 3987.54,2756.46 v1(3981,2763)
SPB: NT3.2 R55.1 TP48.1 | length 1717
  Top Layer w8: NT3.2@4080,2762 4086,2762 v1(4094,2770) ; R55.1@4113.56,1875.56 4113.56,1908.92 v1(4131.85,1927.21)
  Top Layer w10: TP48.1@4083.96,2037.14 4131.85,1989.25 v1(4131.85,1927.21)
  Ground w8: v1(4094,2770) 4115.92,2791.92 4377.08,2791.92 4453.07,2715.93 4453.07,2407.93 4487.54,2373.46 4487.54,2008.47 4448.06,1968.99 4173.63,1968.99 v1(4131.85,1927.21)
SPC: NT7.2 R67.1 TP49.1 | length 1167.7
  Top Layer w8: NT7.2@4196,2762 4202,2762 v1(4210,2770) ; TP49.1@4271.13,2033.14 4343.26,2033.14 4345.26,2035.14 ; v1(4316,2134) 4343.86,2106.14 4345.26,2106.14 4345.26,2035.14 ; R67.1@4356,1880.56 R67.1@4356,1881.12 ; R67.1@4361,1881.12 4361,1911.47 4345.26,1927.21 4345.26,2035.14
  Ground w8: v1(4210,2770) 4221,2759 4317.4,2759 4387.46,2688.94 4387.46,2556 4309,2477.54 4309,2139 4314,2134 v1(4316,2134)
VM: C6.2 C8.2 C57.1 C58.1 F2.2 J5.1 NT12.2 R91.2 TP35.1 U1.30 U1.31 U1.58 U1.59 U1.@3816.59,3188.5 U1.@4257.56,3188.5 | length 1396.8
  Top Layer w10: 3047,4340.69 3047,3640 3367.34,3319.66
  Top Layer w20: 560,3220 681.06,3220 728,3266.94 ; 3046,4340.69 3046,4394.91 R91.2@3047,4395.91
VREF_IN: C55.1 R7.2 TP19.1 U2.1 U2.3 | length 177.6
  Top Layer w10: R7.2@2288,1263.97 2288,1266.37 2316,1294.37 2343.49,1294.37 2364,1314.88 2364,1372.44 2351.4,1385.04 U2.3@2351.4,1388.76
VSENA: C13.2 D12.1 J3.6 R105.2 R106.2 R134.1 U3.1 | length 5410.9
  Top Layer w8: v1@5056.42,961.27 5084.25,933.44 C13.2@5085.23,933.44 ; C13.2@5089,933.44 5089,847.51 D12.1@5132.82,803.69
  Top Layer w10: v1@5059.82,960.9 5059.82,961.93 5045.09,976.66 5045.09,1273.38 5060.68,1288.97 U3.1@5108.79,1288.97 ; J3.6@5129.82,703 5129.82,800.69 D12.1@5132.82,803.69
  Top Layer w15: R106.2@5881,4343.5 5928.29,4343.5 5932,4347.21 ; R134.1@5932,4431.91 5932,4347.21 ; v1(6113.07,4346.07) 5989.36,4346.07 5988,4344.71 5934.5,4344.71 5932,4347.21
  Bottom Layer w8: v1@5059.82,960.9 5084.73,935.98 5319.47,935.98 5344.47,960.98 5976.22,960.98 5982.07,966.84 5982.38,966.84 6153,1137.46 6153,4306.13 v1(6113.07,4346.07)
  other v1: 5056.05,960.9
VSENB: C15.2 D11.1 J3.8 R103.2 R104.2 R130.1 U3.3 | length 5615
  Top Layer w10: U3.3@5108.79,1237.79 5074.5,1237.79 5065,1228.3 5065,1143.96 5157.06,1051.9 v1(5157.06,960.98) ; v1@5157.27,961.19 5185.02,933.44 5186,933.44 5186,846.82 D11.1@5230.82,802 5230.82,704 J3.8@5229.82,703
  Top Layer w15: R103.2@5449.27,4343.02 5454.19,4338.1 5497,4338.1 ; R130.1@5475,4427.91 5478.91,4427.91 5497,4409.82 5497,4338.1 ; v1(5615.69,4337.6) 5614.18,4339.1 5553.69,4339.1 5552.69,4338.1 5497,4338.1
  Bottom Layer w10: v1(5157.06,960.98) 5196.07,1000 5891.45,1000 5891.62,1000.17 5963.08,1000.17 6115,1152.09 6115,4283.32 6056.76,4341.56 5606,4341.56
VSENC: C34.2 D10.1 J3.10 R101.2 R102.2 R116.1 U3.4 | length 5967.8
  Top Layer w10: U3.4@5195.79,1236.21 U3.4@5197.38,1237.79 5240.13,1237.79 5309.73,1168.2 5309.73,959.19 5281.98,931.44 5281,931.44 5281,844.51 D10.1@5325.82,799.69 5327.82,797.69 5327.82,705 J3.10@5329.82,703
  Top Layer w15: R102.2@4995,4339.09 4996.47,4340.56 5033,4340.56 ; R116.1@5023,4432.44 5033,4422.44 5033,4340.56 ; 5049,4341.56 5048.5,4341.06 ; v1(5186,4341.56) 5185.5,4341.06 5048.5,4341.06 ; 5033,4340.56 5048,4340.56 5048.5,4341.06
  Bottom Layer w10: v1(5186,4341.56) 5210,4365.56 6059.63,4365.56 6134,4291.19 6134,1143.91 ; v1(5309.94,958.98) 5309.94,960.9 5329.02,979.98 5969.75,979.98 6133.84,1144.07
VSENVM: C14.2 D9.1 J3.12 R99.2 R100.2 R113.1 U3.6 | length 9622.7
  Top Layer w10: R113.1@3048,4952.09 3048,5290 3534,5776 4906.5,5776 4957.82,5724.69 4957.82,5723.7 4971.52,5710 R99.2@4972.5,5710 ; R99.2@4966.13,5698.73 4976.88,5687.98 4976.88,5634 4976.88,5633.02 4987.63,5622.27 4988.61,5622.27 5092.88,5518 5474,5518 5720,5272 5981,5272 6145.05,5107.95 v1(6189,5107.95) ; U3.6@5197.38,1288.97 5214.44,1288.97 5326.73,1176.68 5326.73,980.72 5375.02,932.44 5376,932.44 5375.56,932 v1(5348.01,932) 5349.63,930.38 5349.63,900.18 5412.82,836.99 D9.1@5412.82,802.69 5429.82,785.69 J3.12@5429.82,703
  Bottom Layer w10: v1(5348.01,932) 5344.47,935.53 5351.93,942.98 5983.67,942.98 5986.29,945.6 5986.6,945.6 6171,1130 6171,4313.59 6168.97,4315.61 6168.97,5087.93 v1(6189,5107.95)
VTEMP: R120.1 TP46.1 U1.3 | length 4688.3
  Top Layer w8: v1(3303,1822) 3303,1895.13 3663.57,2255.71 3663.57,2649.93 3744,2730.36 3744,2880.34 3789.94,2926.28 3843.33,2926.28 3859.91,2942.86 U1.3@3859.91,2964.09 ; v1(3618.8,644.12) 3874.92,388 TP46.1@4742.82,388 TP46.1@4741.13,389.69 ; v1(5059.82,346) 5250.82,346 v1(5279.82,375) ; v1(5408.7,378.13) 5408.7,389.57 R120.1@5435.7,416.57
  Bottom Layer w8: v1(3303,1822) 3303,1456 3356,1403 3359,1403 3541.98,1220.02 3541.98,720.93 v1(3618.8,644.12) ; TP46.1@4742.82,388 4784.82,346 v1(5059.82,346) ; v1(5279.82,375) 5400.82,375 v1@5403.82,378
VTEMP_IN: C53.1 R120.2 R135.1 R137.1 | length 486.5
  Top Layer w10: R135.1@5051.7,467.13 5052.68,467.13 5092.53,427.28 5286.44,427.28 v1(5287.31,428.15) ; v1(5375.7,431.69) 5375.7,458.57 R137.1@5382.7,465.57 5429.58,465.57 R120.2@5435.7,471.69 5435.7,520.57 C53.1@5434.58,521.69 ; C53.1@5429.82,522.44 C53.1@5430.82,521.44
  Bottom Layer w10: v1(5287.31,428.15) 5372.16,428.15 v1(5375.7,431.69)
pads on no net: FID1.1 FID2.1 FID3.1 H9.0 H10.0 H11.0 H12.0 H13.0 H14.0 H15.0 H16.0 J3.5 J3.13 J3.20 J4.6 J4.8 J4.10 J4.12 J4.14 J4.17 J4.18 MH5.1 MH6.1 MH7.1 MH8.1 SH-J1.0 SH-J2.0 SH-J3.0 SH-J4.0 SH-J5.0 U1.1 U1.23 U2.4
copper on no net:
  other v4: 637,64.59 6496,64.59 550.91,114.3 723.09,114.3 6409.91,114.3 6582.09,114.3 550.91,213.7 723.09,213.7 6409.91,213.7 6582.09,213.7 637,263.41 6496,263.41 637,5736.59 6496,5736.59 550.91,5786.3 723.09,5786.3 6409.91,5786.3 6582.09,5786.3 550.91,5885.7 723.09,5885.7 6409.91,5885.7 6582.09,5885.7 637,5935.41 6496,5935.41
